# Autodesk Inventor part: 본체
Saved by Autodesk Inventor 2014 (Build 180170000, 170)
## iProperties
Created: 2026-04
Part Number: 본체
Material: 일반
Document SubType Name: Modeling
Designer: dg
Density: 1 g/cm^3
Appearance: 기본값
Author: dg
Author: jhkim
Creation Date: 2026-03-27
Sending System: Autodesk Inventor 2026
Preprocessor: ST-DEVELOPER v20.1
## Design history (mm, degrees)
node "본체1"
node "솔리드1"
node "기준1"
